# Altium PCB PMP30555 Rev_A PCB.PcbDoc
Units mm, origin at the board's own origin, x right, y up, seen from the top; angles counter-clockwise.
Board outline 51.56 x 17.27 mm, 2 copper layers (Top Layer, Bottom Layer), stack 1.575 mm thick; 27 components, 19 nets, 71 pads, 26 vias.
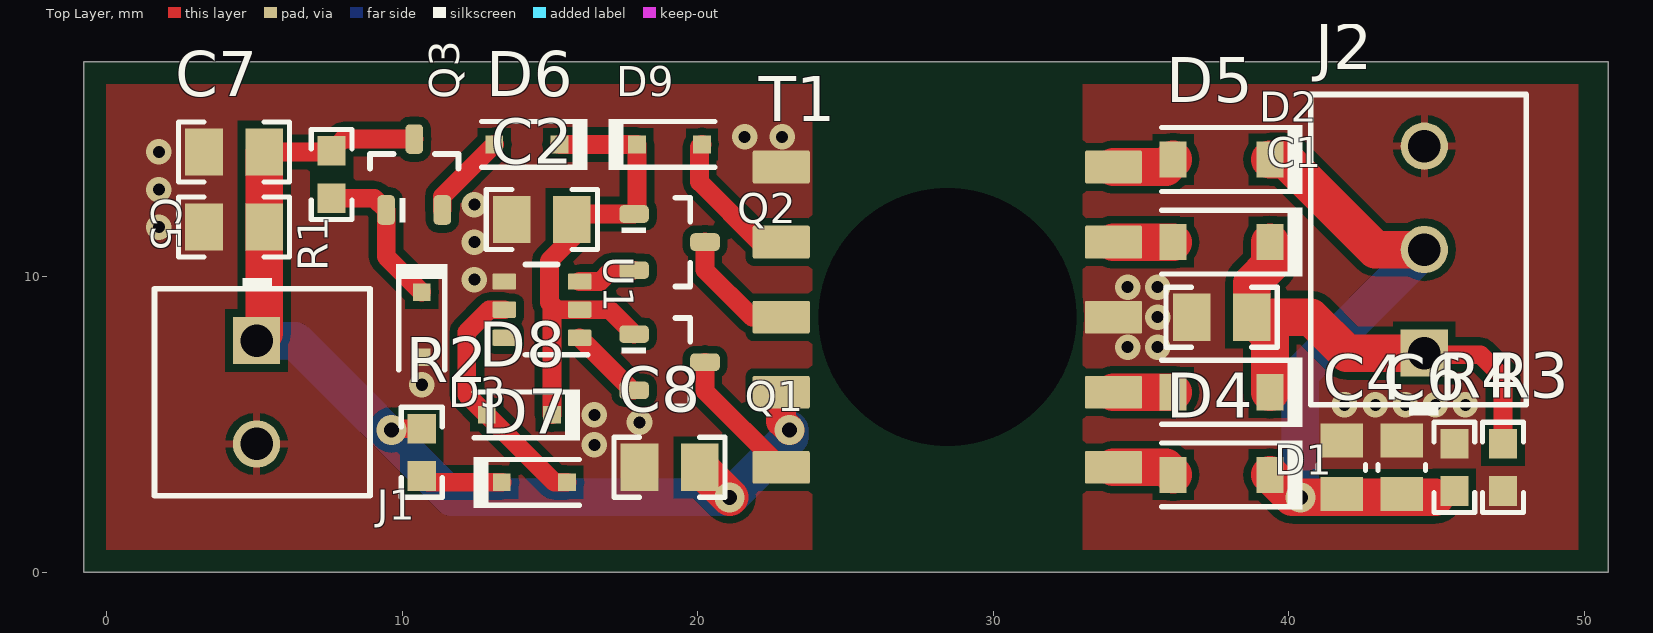
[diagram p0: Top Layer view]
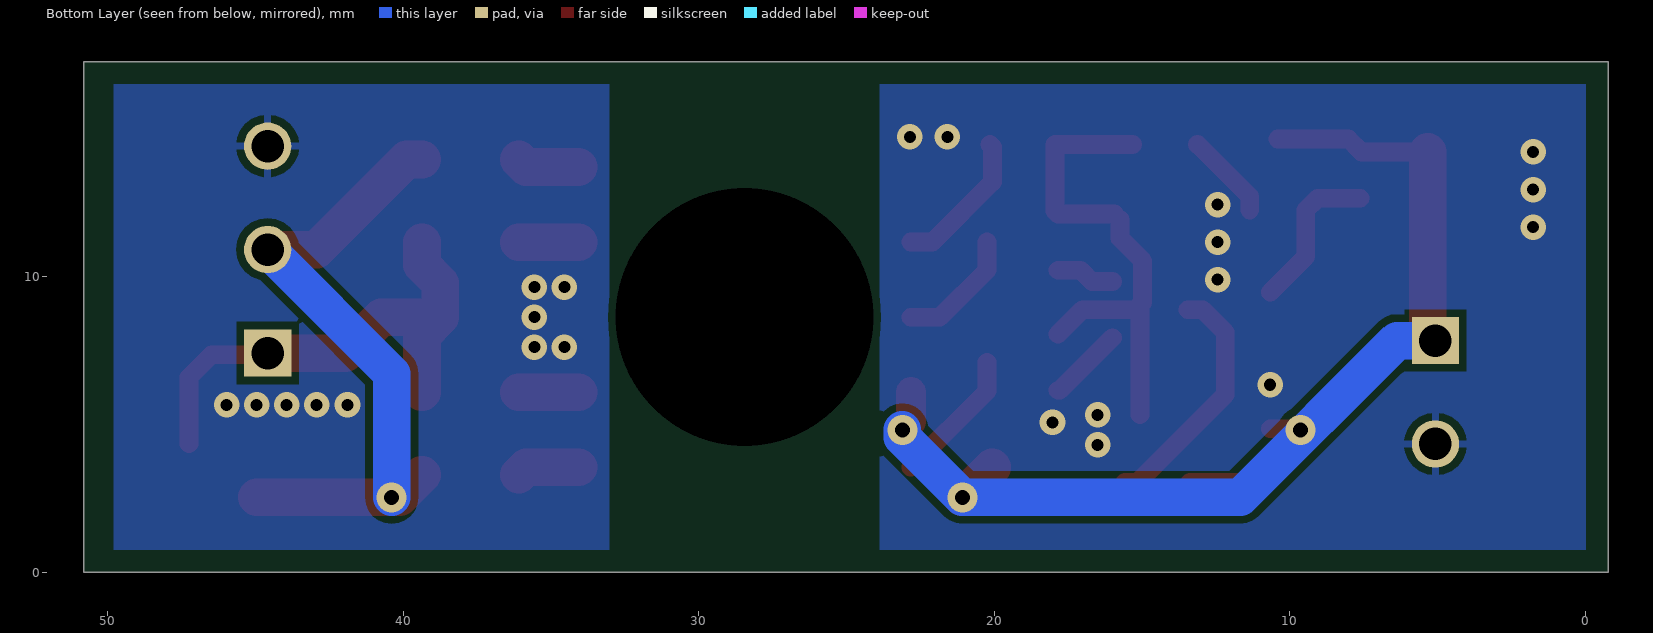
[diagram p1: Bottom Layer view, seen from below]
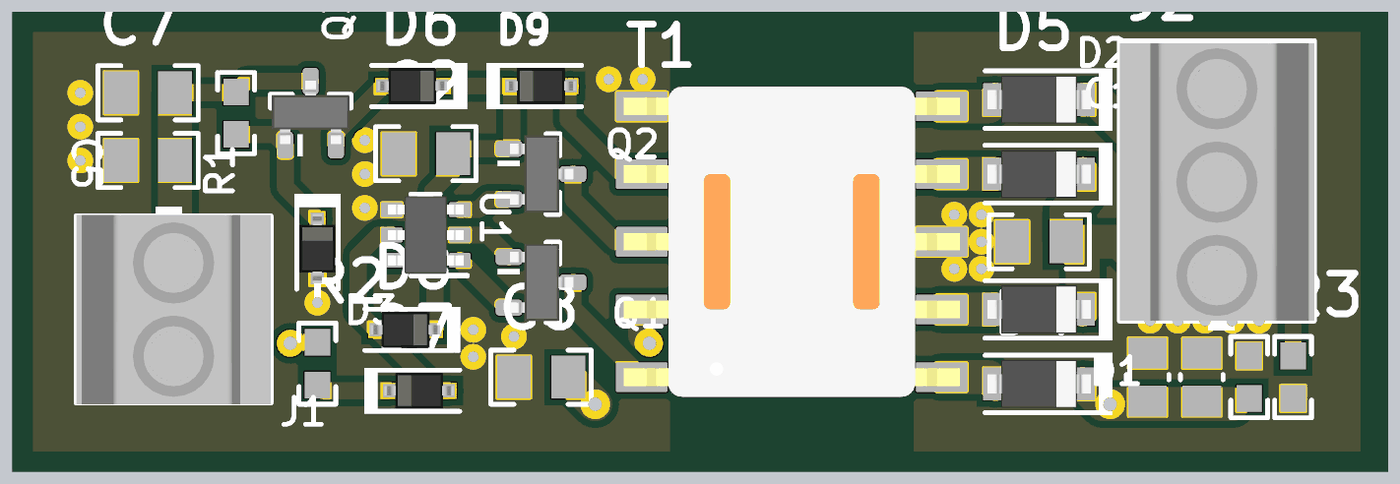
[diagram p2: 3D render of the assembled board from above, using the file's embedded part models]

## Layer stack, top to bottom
Top Solder: solder mask 0.0102, Solder Resist, Dk 3.5
Top Layer: signal copper 0.0356
Dielectric1: core 1.5037, FR-4, Dk 4.8
Bottom Layer: signal copper 0.0356
Bottom Solder: solder mask 0.0102, Solder Resist, Dk 3.5

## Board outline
-0.762,0 -0.762,17.272 50.8,17.272 50.8,0

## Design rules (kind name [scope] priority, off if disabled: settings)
AcuteAngle [All] p1: minimum=4.50000000000000E+0001 checktracksonly=FALSE
AssemblyTestPointUsage [All] p1: valid=2
BoardOutlineClearance BoardOutlineClearance_MountingHoles [OnCopper and InComponentClass('Mounting Holes')] p1: gap=1.016 ignorepadtopadclearanceinfootprint=FALSE
BoardOutlineClearance BoardOutlineClearance_Poly [OnCopper and IsPoly] p2: gap=0.635 ignorepadtopadclearanceinfootprint=FALSE
BoardOutlineClearance [OnCopper and Not InComponentClass('Logo') and not InComponentClass('FiducialMark') and not InRegion(1000,500,4000,800) and not InPoly] p3: gap=1.905 ignorepadtopadclearanceinfootprint=FALSE
Clearance Clearance_4 [InNamedPolygon('TOP_LAYER_GND-S_P006')] p1: gap=0.254 ignorepadtopadclearanceinfootprint=FALSE except(0: Arc-Hole Track-Hole SMDPad-Hole THPad-Hole Via-Hole Fill-Hole Poly-Hole Region-Hole Text-Hole)
Clearance Clearance_3 [InNamedPolygon('BOTTOM_LAYER_GND-S_P004')] p2: gap=0.254 ignorepadtopadclearanceinfootprint=FALSE except(0: Arc-Hole Track-Hole SMDPad-Hole THPad-Hole Via-Hole Fill-Hole Poly-Hole Region-Hole Text-Hole)
Clearance Clearance_2 [InNamedPolygon('BOTTOM_LAYER_GND-P_P002')] p3: gap=0.254 ignorepadtopadclearanceinfootprint=FALSE except(0: Arc-Hole Track-Hole SMDPad-Hole THPad-Hole Via-Hole Fill-Hole Poly-Hole Region-Hole Text-Hole)
Clearance Clearance_1 [InNamedPolygon('TOP_LAYER_GND-P_P000')] p4: gap=0.254 ignorepadtopadclearanceinfootprint=FALSE except(0: Arc-Hole Track-Hole SMDPad-Hole THPad-Hole Via-Hole Fill-Hole Poly-Hole Region-Hole Text-Hole)
Clearance Clearance_Keepouts [((IsTrack Or IsArc) And Not InPoly) And IsFree and IsKeepOut vs ((IsTrack Or IsArc) And Not InPoly) And IsFree and IsKeepOut] p5: gap=0 ignorepadtopadclearanceinfootprint=FALSE
Clearance Clearance_Poly [InPolygon] p6: gap=0.254 ignorepadtopadclearanceinfootprint=FALSE
Clearance Clearance_FiducialMark [IsKeepOut and InComponentClass('FiducialMark') vs IsPad and InComponentClass('FiducialMark')] p7: gap=0 ignorepadtopadclearanceinfootprint=FALSE
Clearance [All] p8: gap=0.2 ignorepadtopadclearanceinfootprint=FALSE except(0: Arc-Hole Track-Hole SMDPad-Hole THPad-Hole Via-Hole Fill-Hole Poly-Hole Region-Hole Text-Hole)
ComponentClearance ComponentClearance_MountingHoles_FiducialMarks [InComponentClass('Mounting Holes') vs InComponentClass('FiducialMark')] p1: gap=1.27 collisioncheckmode=3 verticalgap=0.254 showdistances=FALSE
ComponentClearance ComponentClearance_Shunt [InComponentClass('Header') vs InComponentClass('Shunt')] p2: gap=0 collisioncheckmode=3 verticalgap=0 showdistances=FALSE
ComponentClearance ComponentClearance_Logo [InComponentClass('Logo')] p3: gap=1.27 collisioncheckmode=3 verticalgap=0.254 showdistances=FALSE
ComponentClearance ComponentClearance_ScrewToNut [(HasFootprint('NY PMS 440 0025 PH')) vs (HasFootprint('Keystone_1902C'))] p4: gap=0.127 collisioncheckmode=3 verticalgap=0.254 showdistances=FALSE
ComponentClearance ComponentClearance_MountingHoles [InComponentClass('Mounting Holes')] p5: gap=6.35 collisioncheckmode=3 verticalgap=2540 showdistances=FALSE
ComponentClearance ComponentClearance_SmallPassives [HasFootprint('0201*') or HasFootprint('0402*') or HasFootprint('0508') or HasFootprint('0603*') or HasFootprint('0612') or HasFootprint('0805*') or HasFootprint('0815*') or HasFootprint('0830*') or HasFootprint('1206*') or HasFootprint('1210*') or HasFootprint('1808*') or HasFootprint('1812*') or HasFootprint('1825*') or HasFootprint('2010*') or HasFootprint('2220*') or HasFootprint('2225*') or HasFootprint('2512*') or HasFootprint('2728*') or HasFootprint('3518*') vs HasFootprint('0201*') or HasFootprint('0402*') or HasFootprint('0508') or HasFootprint('0603*') or HasFootprint('0612') or HasFootprint('0805*') or HasFootprint('0815*') or HasFootprint('0830*') or HasFootprint('1206*') or HasFootprint('1210*') or HasFootprint('1808*') or HasFootprint('1812*') or HasFootprint('1825*') or HasFootprint('2010*') or HasFootprint('2220*') or HasFootprint('2225*') or HasFootprint('2512*') or HasFootprint('2728*') or HasFootprint('3518*')] p6: gap=0.38 collisioncheckmode=3 verticalgap=0.254 showdistances=FALSE
ComponentClearance ComponentClearance_THtoSMT [IsThruComponent vs IsSMTComponent] p7: gap=1.016 collisioncheckmode=3 verticalgap=0.762 showdistances=FALSE
ComponentClearance ComponentClearance_THtoTH [IsThruComponent vs IsThruComponent] p8: gap=0.762 collisioncheckmode=3 verticalgap=0.762 showdistances=FALSE
ComponentClearance [All] p9: gap=0.762 collisioncheckmode=3 verticalgap=0.254 showdistances=FALSE
DiffPairsRouting [All] p1: maxlimit=2.54 minlimit=0.254 mostfreqgap=0.254 toplayer_minwidth=0.381 toplayer_maxwidth=0.381 toplayer_prefwidth=0.381 bottomlayer_minwidth=0.381 bottomlayer_maxwidth=0.381 bottomlayer_prefwidth=0.381 maxuncoupledlength=25.4
FabricationTestPointUsage TestPointUsage [All] p1: valid=2 allowmultiple=FALSE
FabricationTestpoint Testpoint [All] p1: side=3 testpointundercomponent=TRUE minsize=1.016 maxsize=2.54 preferedsize=1.524 minholesize=0 maxholesize=1.016 preferedholesize=0.813 testpointgrid=0.025 allowsidetop=TRUE allowsidebottom=TRUE usegrid=TRUE gridtolerance=0
FanoutControl Fanout_LCC [IsLCC] p1: bgadir=Out bgaviamode=Centered fanoutstyle=Auto fanoutdirection=Alternating viagrid=0.025 // Fanout_LCC (Default Rule)
FanoutControl Fanout_BGA [IsBGA] p2: bgadir=Out bgaviamode=Centered fanoutstyle=Auto fanoutdirection=Alternating viagrid=0.025 // Fanout_BGA (Default Rule)
FanoutControl Fanout_Default [All] p4: bgadir=Out bgaviamode=Centered fanoutstyle=Auto fanoutdirection=Alternating viagrid=0.025 // Fanout_Default (Default Rule)
FanoutControl Fanout_Small [(CompPinCount < 5)] p5: bgadir=Out bgaviamode=Centered fanoutstyle=Auto fanoutdirection=OutThenIn viagrid=0.025 // Fanout_Small (Default Rule)
HoleSize [All] p1: absolutevalues=TRUE maxlimit=6.375 minlimit=0.3 maxpercent=80.000 minpercent=20.000
MinimumAnnularRing MinimumAnnularRing_ThermalPadVias [IsVia and InAnyComponent] p1: minimumring=0.15
MinimumAnnularRing [All] p2: minimumring=0.203
MinimumSolderMaskSliver MinimumSolderMaskSliver_Logo [InComponentClass('Logo') vs InComponentClass('Logo')] p1: minsoldermaskwidth=0.018
MinimumSolderMaskSliver [All] p2: minsoldermaskwidth=0.1
PlaneConnect [All] p1: planeconnectstyle=Relief reliefexpansion=0.254 reliefentries=4 reliefconductorwidth=0.254 reliefairgap=0.254
PolygonConnect [All] p1: thpad.connectstyle=Relief thpad.reliefconductorwidth=0.254 thpad.reliefentries=4 thpad.polygonreliefangle="90 Angle" thpad.airgapwidth=0.254 smdpad.connectstyle=Direct smdpad.reliefconductorwidth=0.254 smdpad.reliefentries=4 smdpad.polygonreliefangle="90 Angle" smdpad.airgapwidth=0.254 via.connectstyle=Direct via.reliefconductorwidth=0.254 via.reliefentries=4 via.polygonreliefangle="90 Angle" via.airgapwidth=0.254
RoutingVias ThermalPadVias [IsVia and InAnyComponent] p1: holewidth=0.3 width=0.5 viastyle="Through Hole" minholewidth=0.3 minwidth=0.6 maxholewidth=0.33 maxwidth=0.6
RoutingVias [All] p2: holewidth=0.406 width=0.864 viastyle="Through Hole" minholewidth=0.3 minwidth=0.66 maxholewidth=1.016 maxwidth=1.651
SilkToBoardRegionClearance [Not ((IsComment or IsDesignator) And (Hide <> 'False')) and not InRegion(1000,500,4000,800)] p1:
SilkToSilkClearance SilkToSilkClearance_Pb-FreeLogo [(HasFootprint('Pb-Free_Overlay_Medium') OR HasFootprint('Pb-Free_Overlay_Small')) vs (HasFootprint('Pb-Free_Overlay_Medium') OR HasFootprint('Pb-Free_Overlay_Small'))] p1: silktosilkclearance=0
SilkToSilkClearance [All] p2: silktosilkclearance=0.102
SilkToSolderMaskClearance SilkToComponentPadClearance [(IsPad or IsFill or IsRegion) and InAnycomponent] p1: minsilkscreentomaskgap=0.127 clearancetoexposedcopper=TRUE
SilkToSolderMaskClearance "Silk to Solder Mask Opening" [All] p2: minsilkscreentomaskgap=0.102 clearancetoexposedcopper=FALSE
SolderMaskExpansion [All] p1: expansion=0.05
Width [All] p1: maxlimit=2.54 minlimit=0.152 preferedwidth=0.254 checkconnectedcopper=TRUE
15 further rules are at their usual default settings.

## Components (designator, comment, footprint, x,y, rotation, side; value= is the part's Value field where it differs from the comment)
C1 "885012207026" 0805_HV 37.724,8.636 r180 top value=10uF
C2 "885012207026" 0805_HV 14.732,11.938 r180 top value=10uF
C4 "08053C225KAT2A" 0805_150 41.788,3.556 r90 top value=2.2uF
C5 "08055C105KAT2A" 0805_HV 4.318,11.684 r180 top value=1uF
C6 "08053C225KAT2A" 0805_150 43.82,3.556 r90 top value=2.2uF
C7 "08055C105KAT2A" 0805_HV 4.318,14.224 r180 top value=1uF
C8 "08055C105KAT2A" 0805_HV 19.05,3.556 r180 top value=1uF
D1 "MBR0540T1G" SOD-123 37.724,6.096 r180 top value=40V
D2 "MBR0540T1G" SOD-123 37.724,11.176 r180 top value=40V
D3 "BZT52C5V1S-7-F" SOD-323 10.668,8.382 r270 top value=5.1V
D4 "MBR0580-TP" SOD-123 37.724,3.302 r180 top value=80V
D5 "MBR0580-TP" SOD-123 37.724,13.97 r180 top value=80V
D6 "BAT54WS-7-F" SOD-323 14.224,14.478 r180 top value=30V
D7 "BZX384-C12,115" SOD-323 14.478,3.048 r0 top value=12V
D8 "BAT54WS-7-F" SOD-323 13.97,5.334 r180 top value=30V
D9 "BAT54WS-7-F" SOD-323 19.05,14.478 r0 top value=30V
J1 "39357-0002" MOLEX_39357-0002 5.08,6.096 r270 top
J2 "39357-0003" MOLEX_39357-0003 44.582,10.922 r90 top
Q1 "IRLML0030TRPBF" SOT-23 19.05,7.112 r0 top value=IRLML0100TRPbF
Q2 "IRLML0030TRPBF" SOT-23 19.05,11.176 r0 top value=IRLML0100TRPbF
Q3 "MMBT3904LT1G" SOT-23 10.414,13.462 r90 top value="40 V"
R1 "CRCW0603100KFKEA" 0603 7.62,13.462 r90 top value=100k
R2 "CRCW0603100KFKEA" 0603 10.668,4.064 r90 top value=100k
R3 "ERJ-3EKF1001V" 0603 47.244,3.556 r90 top value=1.00k
R4 "RCG060310K0FKEA" 0603 45.598,3.556 r270 top value=10.0k
T1 "750317843R00" Wurth_750317843R00 28.448,8.636 r90 top
U1 "SN6505BDBVR" DBV0006A_L 14.732,8.89 r180 top

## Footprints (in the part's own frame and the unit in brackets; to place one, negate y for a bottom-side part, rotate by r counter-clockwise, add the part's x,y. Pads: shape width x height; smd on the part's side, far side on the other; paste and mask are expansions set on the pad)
0603 [mm] "0603 from SM-752 data"
  rect 1x0.95 smd: 1(-0.8,0) 2(0.8,0)
  silkscreen extent -1.52,-0.69 1.52,0.69, body extent -0.87,-0.47 0.87,0.47, height 1
0805_150 [mm] "0805 / 1.5 mm height"
  rect 1.15x1.45 smd: 1(-0.9,0) 2(0.9,0)
  silkscreen extent -0.1,-0.8 0.1,0.8, body extent -1.1,-0.72 1.1,0.72, height 1.5
0805_HV [mil] "0805 with 30mil clearance between pads"
  rect 50x63 smd: 1(-40,0) 2(40,0)
  silkscreen extent -74,-40 74,40, body extent -43,-29 43,29, height 57
DBV0006A_L [mm] "SOT23, 6-Leads, Body 2.9x1.6mm, Pitch 0.95mm, Lead Span 2.8mm, IPC High Density"
  rrect18% 0.8x0.55 smd: 1(-1.275,0.95) 2(-1.275,0) 3(-1.275,-0.95) 4(1.275,-0.95) 5(1.275,0) 6(1.275,0.95)
  silkscreen extent -1.55,-1.53 0.55,1.53, body extent -1.42,-1.46 1.42,1.46, height 1.12
MOLEX_39357-0002 [mm] "Terminal Block, 3.5 mm, 2x1, TH"
  rect 1.6x1.6 hole 1.1: 1(-1.75,0)
  round 1.6 hole 1.1: 2(1.75,0)
  silkscreen extent -3.86,-3.45 3.5,3.84, body extent -3.55,-3.45 3.56,3.84, height 8.51
MOLEX_39357-0003 [mm] "Terminal Block, 3.5 mm, 3x1, TH"
  rect 1.6x1.6 hole 1.1: 1(-3.5,0)
  round 1.6 hole 1.1: 2(0,0) 3(3.5,0)
  silkscreen extent -5.61,-3.45 5.25,3.84, body extent -5.25,-3.45 5.16,3.84, height 8.51
SOD-123 [mm] "On Semi recommended land pattern"
  rect 0.915x1.22 smd: 1(-1.637,0) 2(1.637,0)
  silkscreen extent -2.74,-1.17 2.03,1.17, body extent -1.93,-0.9 1.93,0.9, height 1.35
SOD-323 [mm] "NXP recommended land pattern"
  rect 0.6x0.6 smd paste-0.05: 1(-1.1,0) 2(1.1,0)
  silkscreen extent -2.06,-0.86 1.53,0.86, body extent -1.3,-0.67 1.3,0.68, height 1.1
SOT-23 [mm] "SOT23, 3-Leads, Body 2.9x1.3mm, Pitch 0.95mm, Lead Span 2.5mm, IPC Medium Density"
  rrect50% 1x0.6 smd: 1(-1.2,0.95) 2(-1.2,-0.95) 3(1.2,0)
  silkscreen extent -1.63,-1.5 0.7,1.5, body extent -1.16,-1.45 1.21,1.45, height 1
Wurth_750317843R00 [mm] "SMD, 10-Leads, Body 9.25x11.63mm, Pitch 2.54mm"
  rrect9% 1.11x1.93 smd: 1(-5.08,5.62) 2(-2.54,5.62) 3(0,5.62) 4(2.54,5.62) 5(5.08,5.62) 6(5.08,-5.62) 7(2.54,-5.62) 8(0,-5.62) 9(-2.54,-5.62) 10(-5.08,-5.62)
  round 8.43 hole 8.73 unplated mask+0.102: ""(0,0)
  body extent -5.82,-6.3 5.81,6.3, height 1.98

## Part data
C1 C2: library part CMP-0007691-2, "CAP, CERM, 10 uF, 10 V, +/- 10%, X7R, 0805", Cap_Case=0805, Manufacturer="Wurth Elektronik", Supplier Part Number 1=710-885012207026, TempCo=X7R, Tolerance_%=10%, Value1=Unknown, Value2=10V, ValueDisplayed=10uF
C4 C6: library part CMP-0007573-2, "CAP, CERM, 2.2 uF, 25 V, +/- 10%, X7R, 0805", Cap_Case=0805, Manufacturer=AVX, Supplier Part Number 1=478-5719-1-ND, TempCo=X7R, Tolerance_%=10%, Value1=Unknown, Value2=25V, ValueDisplayed=2.2uF
C5 C7 C8: library part CMP-0007634-2, "CAP, CERM, 1 uF, 50 V, +/- 10%, X7R, 0805", Cap_Case=0805, Manufacturer=AVX, Supplier Part Number 1=478-7956-1-ND, TempCo=X7R, Tolerance_%=10%, Value1=Unknown, Value2=50V, ValueDisplayed=1uF
D1 D2: "Diode, Schottky, 40 V, 0.5 A, SOD-123", Manufacturer="ON Semiconductor", Supplier Part Number 1=MBR0540T1GOSCT-ND, Value1=0.5A, Value2=0.51V
D3: library part CMP-0005865-1, "Diode, Zener, 5.1 V, 200 mW, SOD-323", Manufacturer="Diodes Inc.", Power_W=200mW, Supplier Part Number 1=BZT52C5V1S-FDICT-ND, Value1=0.2W
D4 D5: library part CMP-0077000-1, "Diode, Schottky, 80 V, 0.5 A, SOD-123", Manufacturer="Micro Commercial Components", Supplier Part Number 1=MBR0580-TPMSCT-ND, Value1=0.5A, Value2=0.8V
D6 D8 D9: library part CMP-0028458-1, "Diode, Schottky, 30 V, 0.2 A, SOD-323", Manufacturer="Diodes Inc.", Supplier Part Number 1=BAT54WS-FDICT-ND, Value1=0.2A, Value2=0.7V
D7: library part CMP-0005843-2, "Diode, Zener, 12 V, 300 mW, SOD-323", Manufacturer="NXP Semiconductor", Power_W=300mW, Supplier Part Number 1=568-6279-1-ND, Value1=0.3W
J1: library part CMP-0055341-1, "Terminal Block, 3.5 mm, 2x1, Tin, TH", Manufacturer=Molex, Supplier Part Number 1=WM7877-ND
J2: library part CMP-0055340-1, "Terminal Block, 3.5 mm, 3x1, Tin, TH", Manufacturer=Molex, Supplier Part Number 1=WM7878-ND
Q1 Q2: library part CMP-0000635-1, "MOSFET, N-CH, 100 V, 1.6 A, SOT-23", Alternate Manufacturer=None, Manufacturer="International Rectifier", PartNumber=IRLML0100TRPbF, Supplier Part Number 1=IRLML0100TRPBFTR-ND, Value1=0, Value2="2.5 nC"
Q3: library part "MMBT3904LT1G, ON Semiconductor", "Transistor, NPN, 40 V, 0.2 A, SOT-23", Manufacturer="ON Semiconductor", Supplier Part Number 1=MMBT3904LT1GOSCT-ND, Value1="0.2 A", Value2=300
R1 R2: library part CMP-0021990-4, "RES, 100 k, 1%, 0.1 W, AEC-Q200 Grade 0, 0603", Manufacturer=Vishay-Dale, Power_W=100mW, Supplier Part Number 1=541-100KHCT-ND, TempCo="100 ppm/C", Tolerance_%=1%, Value2=0.1W, Value_Code=100k
R3: library part CMP-0022680-4, "RES, 1.00 k, 1%, 0.1 W, 0603", Manufacturer=Panasonic, Power_W=100mW, Supplier Part Number 1=P1.00KHCT-ND, TempCo="100 ppm/C", Tolerance_%=1%, Value2=0.1W, Value_Code=1k00, ValueDisplayed=1.00k
R4: library part CMP-0023337-3, "RES, 10.0 k, 1%, 0.1 W, 0603", Manufacturer="Vishay Draloric", Power_W=100mW, Supplier Part Number 1=541-1784-1-ND, TempCo="100 ppm/C", Tolerance_%=1%, Value2=0.1W, Value_Code=10k0, ValueDisplayed=10.0k
T1: library part CMP-0083966-1, "Transformer, 3430 uH, SMT", Manufacturer="Wurth Elektronik"
U1: library part CMP-0076095-1, "Low-Noise 1 A, 420 kHz Transformer Driver, DBV0006A (SOT-23-6)", Alternate Manufacturer="Texas Instruments", Alternate PartNumber=SN6505BDBVT

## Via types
v1: diameter 0.864, hole 0.406, Top Layer to Bottom Layer, 22 vias
v2: diameter 1.016, hole 0.508, Top Layer to Bottom Layer, 4 vias

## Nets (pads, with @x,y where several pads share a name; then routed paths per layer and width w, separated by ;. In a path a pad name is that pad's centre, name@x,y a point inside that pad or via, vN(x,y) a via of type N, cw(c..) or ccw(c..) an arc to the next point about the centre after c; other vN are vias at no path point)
GND-P: C2.2 C5.2 C7.2 C8.2 D3.2 J1.2 T1.5 U1.4
  other v1: 16.51,4.318 18.034,5.08 16.51,5.334 10.668,6.35 12.446,9.906 12.446,11.176 1.778,11.684 12.446,12.446 1.778,12.954 1.778,14.224 21.59,14.732 22.86,14.732
GND-S: C1.2 C4.2 C6.2 J2.3 R3.1 R4.1 T1.8
  other v1: 41.882,5.672 42.926,5.672 43.942,5.672 44.958,5.672 45.974,5.672 34.544,7.62 35.56,7.62 35.56,8.636 34.544,9.652 35.56,9.652
NetC1_1: C1.1 D1.1 D2.1 J2.1 R3.2 | length 17.1
  Top Layer w0.635: J2.1@44.638,7.366 46.482,7.366 47.244,6.604 R3.2
  Top Layer w1.27: D1.1 39.362,8.014 C1.1 ; D2.1 39.362,10.406 38.74,9.784 C1.1 ; J2.1 41.956,7.422 40.742,8.636 C1.1
NetC2_1: C2.1 D6.1 D8.1 D9.1 Q1.1 Q2.1 U1.2 | length 17.1
  Top Layer w0.635: D8.1 15.07,9.052 ; D6.1 D9.1 17.95,12.226 Q2.1 C2.1@15.936,12.126 ; C2.1 15.748,11.302 14.986,10.54 14.986,9.136 15.07,9.052 ; Q1.1 17.022,8.89 U1.2 15.232,8.89 15.07,9.052
NetC4_1: C4.1 C6.1 D4.1 D5.1 J2.2 R4.2 | length 22.5
  Top Layer w1.27: D4.1 40.124,2.54 v2(40.386,2.54) 44.958,2.54 ; D5.1 39.878,13.97 42.926,10.922 J2.2
  Bottom Layer w1.27: v2(40.386,2.54) 40.386,6.726 J2.2
NetC5_1: C5.1 C7.1 C8.1 J1.1 Q3.3 R1.2 R2.2 T1.2 | length 36.9
  Top Layer w0.635: C7.1 7.582,14.224 R1.2 8.02,14.662 Q3.3 ; v2(9.652,4.826) 9.69,4.864 R2.2
  Top Layer w1.016: T1.2 22.828,5.112 v2(23.114,4.826)
  Top Layer w1.27: J1.1 5.334,8.1 C5.1 C7.1 ; C8.1 v2(21.082,2.54)
  Bottom Layer w1.27: J1.1 6.378,7.846 11.684,2.54 v2(21.082,2.54) 23.114,4.572 v2(23.114,4.826)
NetD1_2: D1.2 T1.9 | length 2
  Top Layer w1.27: T1.9 D1.2
NetD2_2: D2.2 T1.7 | length 2
  Top Layer w1.27: T1.7 D2.2
NetD3_1: D3.1 Q3.1 R1.1 | length 5.3
  Top Layer w0.635: R1.1 9.064,12.662 Q3.1 9.464,10.686 D3.1
NetD4_2: D4.2 T1.10 | length 2.1
  Top Layer w1.27: T1.10 35.833,3.556 D4.2
NetD5_2: D5.2 T1.6 | length 2.1
  Top Layer w1.27: T1.6 35.833,13.716 D5.2
NetD6_2: D6.2 Q3.2 | length 2.9
  Top Layer w0.635: Q3.2 11.364,12.718 D6.2
NetD7_1: D7.1 R2.1 | length 2.5
  Top Layer w0.635: R2.1@10.884,3.048 D7.1
NetD7_2: D7.2 D8.2 U1.5 | length 8.3
  Top Layer w0.635: U1.5 12.954,8.89 12.192,8.128 12.192,6.012 D8.2 15.156,3.048 D7.2
NetD9_2: D9.2 T1.4 | length 4.9
  Top Layer w0.635: D9.2 20.066,14.394 20.066,13.208 22.098,11.176 T1.4
NetQ1_2: Q1.2 U1.1 | length 2.6
  Top Layer w0.635: U1.1 17.785,6.162 Q1.2
NetQ1_3: Q1.3 T1.1 | length 4.6
  Top Layer w0.635: Q1.3 20.25,6.134 T1.1
NetQ2_2: Q2.2 U1.3 | length 2
  Top Layer w0.635: U1.3 16.698,9.84 17.084,10.226 Q2.2
NetQ2_3: Q2.3 T1.3 | length 4.2
  Top Layer w0.635: Q2.3 20.25,10.23 21.844,8.636 T1.3
pads on no net: T1. U1.6

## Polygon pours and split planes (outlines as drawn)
GND-S on Top Layer "Top Layer-No Net 1" (solid, pour order 4): 33.02,16.51 49.784,16.51 49.784,0.762 33.02,0.762
GND-P on Top Layer "Top Layer-No Net" (solid, pour order 0): 0,16.51 23.876,16.51 23.876,0.762 0,0.762
GND-S on Bottom Layer "Top Layer-No Net 1" (solid, pour order 6): 33.02,16.51 49.784,16.51 49.784,0.762 33.02,0.762
GND-P on Bottom Layer "Top Layer-No Net" (solid, pour order 2): 0,16.51 23.876,16.51 23.876,0.762 0,0.762

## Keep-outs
Keep-Out Layer:
  text ".Layer_Name" at 14.656,-21.806 h1.52

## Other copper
Top Layer:
  text ".Layer_Name" at 14.656,-21.806 h1.52
Bottom Layer:
  text ".Layer_Name" at 14.656,-21.806 h1.52

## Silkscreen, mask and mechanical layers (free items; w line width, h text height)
Top Overlay:
  text ".Layer_Name" at 14.656,-21.806 h1.52
Bottom Overlay:
  text ".Layer_Name" at 14.656,-21.806 h1.52
Top Paste:
  text ".Layer_Name" at 14.656,-21.806 h1.52
Bottom Paste:
  text ".Layer_Name" at 14.656,-21.806 h1.52
Top Solder:
  text ".Layer_Name" at 14.656,-21.806 h1.52
  text ".Layer_Name" at 14.656,-21.806 h1.52
Bottom Solder:
  text "A" at 6.096,14.164 h2.54
  text "'.PRJ_Number'.PCB_Rev-" at 19.05,14.164 h2.75
  text ".Layer_Name" at 14.656,-21.806 h1.52
Drill Guide:
  text ".Layer_Name" at 14.656,-21.806 h1.52
M1 Board Outline:
  the board outline again, w0.254
  text ".Layer_Name" at 14.656,-21.806 h1.52
M2 Board Dimensions:
  rectangle: 0,-6.985 3.175,-3.81
  rectangle: 3.175,-10.16 12.7,-6.985
  lines w0.178: 0,-6.985 25.4,-6.985 ; 3.175,-10.16 3.175,-3.81 ; 6.35,-10.16 6.35,-3.81 ; 12.7,-10.16 12.7,-3.81 ; 19.05,-10.16 19.05,-3.81 ; 0,-10.16 25.4,-10.16 25.4,-3.81 0,-3.81 0,-10.16
  text ".Layer_Name" at 14.656,-21.806 h1.52
M3 3D STEP Top:
  text ".Layer_Name" at 14.656,-21.806 h1.52
M4 3D STEP Bottom:
  text ".Layer_Name" at 14.656,-21.806 h1.52
M5 Assembly Top:
  lines w0.254: -7.417,-23.626 160.223,-23.626 ; -7.417,-18.462 160.274,-18.462 ; -7.417,-13.297 -7.417,-28.791 94.31,-28.791 160.274,-28.791 160.274,-13.297 -7.404,-13.297 -7.404,-28.791 32.614,-28.791 ; 55.194,-28.791 55.194,-13.297 ; 87.376,-18.462 87.376,-13.297 ; 108.712,-18.462 108.712,-13.297 ; 124.511,-28.956 124.511,-23.804
  text "COMPONENTS MARKED 'DNP' SHOULD NOT BE POPULATED." at 29.299,-8.09 h1.52
  text "ASSEMBLY VARIANT:" at 29.286,-11.024 h1.52
  text ".VariantName" at 55.601,-11.024 h1.52
  text "PCB VIEWED FROM TOP SIDE" at -5.804,-16.654 h1.52
  text "BOARD #:" at 57.099,-16.654 h1.52
  text ".PRJ_Number" at 70.955,-16.654 h1.52
  text "REV:" at 92.405,-16.654 h1.52
  text ".PCB_Rev" at 99.809,-16.654 h1.52
  text "SVN REV:" at 113.69,-16.654 h1.52
  text ".VersionControl_RevNumber" at 126.543,-16.654 h1.52
  text "TID #:" at 57.099,-21.819 h1.52
  text ".TID" at 70.955,-21.819 h1.52
  text "PLOT NAME =" at -5.804,-27.034 h1.52
  text ".plot_File_Name" at 14.656,-27.034 h1.52
  text "GENERATED    :" at 57.15,-27.034 h1.52
  text ".Print_Date" at 79.235,-27.034 h1.52
  text ".Print_Time" at 97.752,-27.034 h1.52
  text "TEXAS INSTRUMENTS" at 129.87,-27.034 h1.52
M6 Assembly Bottom:
  lines w0.254: -7.429,-18.474 160.261,-18.474 ; -7.379,-23.639 160.261,-23.639 ; 28.334,-28.969 28.334,-23.817 ; 44.133,-18.474 44.133,-13.31 ; 65.468,-18.474 65.468,-13.31 ; 97.65,-28.804 97.65,-13.31 ; 120.231,-28.804 160.249,-28.804 160.249,-13.31 -7.429,-13.31 -7.429,-28.804 58.534,-28.804 160.261,-28.804 160.261,-13.31
  text "COMPONENTS MARKED 'DNP' SHOULD NOT BE POPULATED." at 154.991,-8.077 h1.52
  text ".VariantName" at 128.473,-11.024 h1.52
  text "ASSEMBLY VARIANT:" at 154.864,-11.024 h1.52
  text ".VersionControl_RevNumber" at 26.302,-16.667 h1.52
  text "SVN REV:" at 39.154,-16.667 h1.52
  text ".PCB_Rev" at 53.035,-16.667 h1.52
  text "REV:" at 60.439,-16.667 h1.52
  text ".PRJ_Number" at 81.89,-16.667 h1.52
  text "BOARD #:" at 95.745,-16.667 h1.52
  text "PCB VIEWED FROM BOTTOM SIDE" at 158.648,-16.667 h1.52
  text ".TID" at 81.89,-21.831 h1.52
  text "TID #:" at 95.745,-21.831 h1.52
  text "TEXAS INSTRUMENTS" at 22.974,-27.047 h1.52
  text ".Print_Time" at 55.093,-27.047 h1.52
  text ".Print_Date" at 73.609,-27.047 h1.52
  text "GENERATED    :" at 95.694,-27.047 h1.52
  text ".plot_File_Name" at 138.189,-27.047 h1.52
  text "PLOT NAME =" at 158.648,-27.047 h1.52
M9 Title Sheet:
  drawing of 57 lines, arcs and shapes, not listed
  text "1" at 18.792,204.127 h1.78
  text "2" at 82.182,204.127 h1.78
  text "3" at 145.411,204.127 h1.78
  text "4" at 209.08,204.127 h1.78
  text "5" at 272.555,204.127 h1.78
  text "6" at 336.182,204.127 h1.78
  text "A" at -10.579,175.095 h1.78
  text "A" at 365.341,175.095 h1.78
  text "B" at -10.579,114.643 h1.78
  text "B" at 365.341,114.643 h1.78
  text "C" at -10.579,54.318 h1.78
  text "C" at 365.341,54.318 h1.78
  text "PROJECT TITLE:" at 288.125,7.048 h1.14
  text ".PRJ_Title" at 289.395,3.662 h1.78
  text "DESIGNED FOR:" at 288.125,-0.597 h1.14
  text ".PRJ_Customer" at 289.395,-4.153 h1.78
  text "D" at -10.579,-5.88 h1.78
  text "D" at 365.341,-5.88 h1.78
  text "FILE NAME:" at 288.125,-8.217 h1.14
  text ".PCB_File_Name_No_Path" at 289.395,-11.265 h1.78
  text "Texas Instruments (TI) and/or its licensors do not warrant the accuracy or completeness of this specification" at 161.9,-15.376 h1.14
  text "ENGINEER:" at 288.125,-15.583 h1.14
  text "LAYOUT BY:" at 326.352,-15.583 h1.14
  text "or any information contained therein. TI and/or its licensors do not warrant that this design will meet" at 160.757,-18.237 h1.14
  text ".PRJ_Engineer" at 289.395,-19.52 h1.78
  text ".PCB_Layout" at 327.635,-19.52 h1.78
  text "the specifications, will be suitable for your application or fit for any particular purpose, or will operate in" at 160.757,-21.099 h1.14
  text ".Layer_Name" at 14.656,-21.806 h1.52
  text "ALTIUM DESIGNER VERSION:" at 326.352,-23.457 h1.14
  text "an implementation. TI and/or its licensors do not warrant that the design is production worthy. You should" at 160.757,-23.961 h1.14
  text "completely validate and test your design implementation to confirm the system functionality for your application." at 161.9,-26.822 h1.14
  text ".print_Scale" at 289.395,-26.843 h1.78
  text ".Application_BuildNumber" at 327.635,-26.843 h1.78
  text "1" at 18.792,-32.093 h1.78
  text "2" at 82.182,-32.093 h1.78
  text "3" at 145.411,-32.093 h1.78
  text "4" at 209.08,-32.093 h1.78
  text "5" at 272.555,-32.093 h1.78
  text "6" at 336.182,-32.093 h1.78
M10 Fab Notes:
  drawing of 189 lines, arcs and shapes, not listed
  text "DESIGN INFORMATION" at 314.503,161.447 h1.52
  text "MIN. TRACK WIDTH:" at 298.131,158.091 h1.52
  text "8" at 325.976,158.091 h1.52
  text "MIL" at 329.907,158.091 h1.52
  text "MIN. CLEARANCE:" at 298.131,154.938 h1.52
  text "0.2" at 324.452,154.938 h1.52
  text "mm" at 329.907,154.938 h1.52
  text "MIN. VIA PAD SIZE:" at 298.131,151.785 h1.52
  text "24" at 325.214,151.785 h1.52
  text "MIL" at 329.907,151.785 h1.52
  text "0.05mm (2MIL)" at 315.784,148.486 h1.52
  text "MINIMUM ANNULAR RING" at 289.769,148.277 h1.52
  text "EXTERNAL" at 333.768,148.277 h1.52
  text "PER" at 294.849,145.48 h1.52
  text "IPC-D-275 CLASS 2 LEVEL C" at 300.437,145.48 h1.52
  text "MIL, HOLES" at 338.238,142.928 h1.52
  text "+/-" at 328.27,142.709 h1.52
  text "+/-" at 349.961,142.709 h1.52
  text "REGISTRATION TOLERANCES:" at 289.769,142.682 h1.52
  text "METAL" at 320.243,142.682 h1.52
  text "5" at 334.879,142.683 h1.52
  text "3" at 356.037,142.683 h1.52
  text "MIL" at 358.99,142.682 h1.52
  text "HOLE SIZE TOLERANCE (UNLESS OTHERWISE SPECIFIED):" at 289.769,140.185 h1.52
  text "+/-" at 349.961,140.112 h1.52
  text "3" at 356.037,140.085 h1.52
  text "MIL" at 358.99,140.085 h1.52
  text "MATERIAL:" at 287.87,136.589 h1.52
  text "FR-4 High Tg" at 312.926,133.324 h1.52
  text "X" at 309.257,133.122 h1.52
  text "FR-408" at 298.563,133.007 h1.52
  text "OTHER" at 336.358,133.007 h1.52
  text "62 MIL (1.6mm) +/-10%" at 306.694,129.374 h1.52
  text "X" at 303.643,129.312 h1.52
  text "THICKNESS:" at 289.769,129.165 h1.52
  text "OTHER" at 339.33,129.165 h1.52
  text "TOLERANCE:" at 289.769,125.652 h1.52
  text "X" at 311.314,125.652 h1.52
  text "ANSI IPC-6012 TYPE 3 CLASS 2" at 315.836,125.652 h1.52
  text "OTHER +/-" at 315.835,121.989 h1.52
  text "BOW & TWIST:" at 289.769,118.302 h1.52
  text "X" at 311.314,118.302 h1.52
  text "ANSI IPC-6012 TYPE 3 CLASS 2" at 315.836,118.302 h1.52
  text "OTHER +/-" at 315.835,114.576 h1.52
  text "DRILLING:" at 287.87,111.258 h1.52
  text "NC_DRILL FILES" at 332.599,108.586 h1.52
  text "REFERENCE:" at 289.769,108.486 h1.52
  text "X" at 306.463,108.484 h1.52
  text "AS SHOWN" at 310.984,108.486 h1.52
  text "X" at 329.348,108.486 h1.52
  text "OTHER" at 340.168,104.873 h1.52
  text "PTH COPPER THICKNESS:" at 289.761,104.783 h1.52
  text "X" at 318.697,104.783 h1.52
  text "20-30 um" at 321.948,104.783 h1.52
  text "BOARD FINISH:" at 287.87,101.034 h1.52
  text "SILKSCREEN:" at 291.812,98.237 h1.52
  text "X" at 316.14,98.237 h1.52
  text "TOP" at 319.112,98.237 h1.52
  text "X" at 329.094,98.237 h1.52
  text "BOTTOM" at 332.091,98.237 h1.52
  text "SILKSCREEN COLOR:" at 291.812,94.295 h1.52
  text "X" at 316.115,94.295 h1.52
  text "WHITE" at 319.112,94.295 h1.52
  text "OTHER" at 332.091,94.295 h1.52
  text "X" at 319.442,90.652 h1.52
  text "GREEN" at 322.439,90.652 h1.52
  text "OTHER" at 338.136,90.652 h1.52
  text "SOLDER RESIST COLOR:" at 291.812,90.477 h1.52
  text "X" at 319.442,86.734 h1.52
  text "MATTE" at 322.439,86.734 h1.52
  text "SEMI-GLOSS" at 338.125,86.717 h1.52
  text "IMMERSION GOLD (ENIG)" at 314.819,82.345 h1.52
  text "ENEPIG" at 348.793,82.162 h1.52
  text "SURFACE FINISH:" at 287.87,82.136 h1.52
  text "X" at 310.298,82.136 h1.52
  text "IMM. TIN/SILVER OR EQUIV" at 296.24,78.649 h1.52
  text "OTHER" at 332.599,78.549 h1.52
  text "ARRAY/PANEL:" at 287.87,74.602 h1.52
  text "CUT AND TRIM PER M1 BOARD OUTLINE" at 314.819,74.393 h1.52
  text "N.C. ROUTE" at 314.819,70.94 h1.52
  text "X" at 332.295,70.94 h1.52
  text "V. SCORE" at 336.816,70.94 h1.52
  text "CERTIFICATION:" at 287.87,67.66 h1.52
  text "MATERIALS AND WORKMANSHIP FOR ALL PCBS" at 306.285,67.66 h1.52
  text "TO MEET OR EXCEED THE REQUIREMENTS OF:" at 306.285,65.271 h1.52
  text "X" at 297.078,62.003 h1.52
  text "ANSI IPC-A-600F CLASS ->" at 300.329,62.003 h1.52
  text "X" at 342.188,62.003 h1.52
  text "2" at 344.982,62.003 h1.52
  text "1" at 336.981,61.965 h1.52
  text "3" at 353.973,61.965 h1.52
  text "X" at 317.702,58.252 h1.52
  text "RoHS" at 320.953,58.252 h1.52
  text "OTHER" at 337.321,58.252 h1.52
  text "PER ORDER" at 347.407,58.252 h1.52
  text "ALL BOARDS MUST MEET OR EXCEED UL94-V0 REQUIREMENTS." at 288.569,54.345 h1.52
  text "PCB MUST BEAR THE UL94V-0 UL REGISTERED MATERIAL ID NUMBER" at 288.569,51.397 h1.52
  text "ADDITIONAL REQUIREMENTS:" at 287.87,47.094 h1.52
  text "MICROSECTION:" at 289.769,44.373 h1.52
  text "YES" at 312.775,44.373 h1.52
  text "REQUIRED" at 334.657,40.707 h1.52
  text "BARE BOARD ELEC. TEST:" at 289.769,40.634 h1.52
  text "NONE" at 322.935,40.634 h1.52
  text "X" at 331.66,40.634 h1.52
  text "PER ORDER" at 349.693,40.634 h1.52
  text "XX MIL VIAS REQUIRE NON-CONDUCTIVE FILL AND PLANARIZE" at 294.04,35.428 h1.5
  text "XX MIL VIAS REQUIRE CONDUCTIVE FILL AND PLANARIZE" at 294.243,32.787 h1.52
  text "OUTER XX MIL TRACES REQUIRE 50 OHM SINGLE-ENDED IMPEDANCE" at 294.218,28.637 h1.47
  text "LAYER 2 & 3 (INNER LAYERS) XX MIL WIDE, XX MIL SPACE / TRACES REQUIRE 100 OHM DIFFERENTIAL IMPEDANCE" at 294.015,22.65 h1.52
  text ".Layer_Name" at 14.656,-21.806 h1.52
M11 Gerber Information:
  lines w0.254: -7.417,-23.626 160.223,-23.626 ; -7.417,-18.462 160.274,-18.462 ; -7.417,-13.297 -7.417,-28.791 94.31,-28.791 160.274,-28.791 160.274,-13.297 -7.404,-13.297 -7.404,-28.791 32.614,-28.791 ; 55.194,-28.791 55.194,-13.297 ; 87.376,-18.462 87.376,-13.297 ; 108.712,-18.462 108.712,-13.297 ; 124.511,-28.956 124.511,-23.804
  text "ALL ARTWORK VIEWED FROM TOP SIDE" at -5.804,-16.654 h1.52
  text "BOARD #:" at 57.099,-16.654 h1.52
  text ".PRJ_Number" at 70.955,-16.654 h1.52
  text "REV:" at 92.405,-16.654 h1.52
  text ".PCB_Rev" at 99.809,-16.654 h1.52
  text "SVN REV:" at 113.69,-16.654 h1.52
  text ".VersionControl_RevNumber" at 126.543,-16.654 h1.52
  text "LAYER NAME =" at -5.804,-21.806 h1.52
  text "TID #:" at 57.099,-21.819 h1.52
  text ".TID" at 70.955,-21.819 h1.52
  text "PLOT NAME =" at -5.804,-27.034 h1.52
  text ".plot_File_Name" at 14.656,-27.034 h1.52
  text "GENERATED    :" at 57.15,-27.034 h1.52
  text ".Print_Date" at 79.235,-27.034 h1.52
  text ".Print_Time" at 97.752,-27.034 h1.52
  text "TEXAS INSTRUMENTS" at 129.87,-27.034 h1.52
M12 Stackup:
  drawing of 191 lines, arcs and shapes, not listed
  text "Layer" at 248.865,198.31 h1.52
  text "Name" at 259.277,198.31 h1.52
  text "Material" at 282.892,198.31 h1.52
  text "Thickness" at 304.731,198.31 h1.52
  text "Constant" at 321.236,198.31 h1.52
  text "Board Layer Stack" at 335.711,198.31 h1.52
  text "1" at 248.865,195.262 h1.52
  text "Top Overlay" at 259.277,195.262 h1.52
  text "2" at 248.865,192.214 h1.52
  text "Top Solder" at 259.277,192.214 h1.52
  text "Solder Resist" at 282.892,192.214 h1.52
  text "0.40mil" at 304.731,192.214 h1.52
  text "3.5" at 321.236,192.214 h1.52
  text "3" at 248.865,189.166 h1.52
  text "Top Layer" at 259.277,189.166 h1.52
  text "Copper" at 282.892,189.166 h1.52
  text "1.40mil" at 304.731,189.166 h1.52
  text "4" at 248.865,186.118 h1.52
  text "Dielectric1" at 259.277,186.118 h1.52
  text "FR-4" at 282.892,186.118 h1.52
  text "59.20mil" at 304.731,186.118 h1.52
  text "4.8" at 321.236,186.118 h1.52
  text "5" at 248.865,183.07 h1.52
  text "Bottom Layer" at 259.277,183.07 h1.52
  text "Copper" at 282.892,183.07 h1.52
  text "1.40mil" at 304.731,183.07 h1.52
  text "6" at 248.865,180.022 h1.52
  text "Bottom Solder" at 259.277,180.022 h1.52
  text "Solder Resist" at 282.892,180.022 h1.52
  text "0.40mil" at 304.731,180.022 h1.52
  text "3.5" at 321.236,180.022 h1.52
  text "7" at 248.865,176.975 h1.52
  text "Bottom Overlay" at 259.277,176.975 h1.52
  text ".Layer_Name" at 14.656,-21.806 h1.52
M13 Component Bodies Top:
  text ".Layer_Name" at 14.656,-21.806 h1.52
M14 Component Bodies Bottom:
  text ".Layer_Name" at 14.656,-21.806 h1.52
M15 Courtyards Top:
  text ".Layer_Name" at 14.656,-21.806 h1.52
M16 Courtyards Bottom:
  text ".Layer_Name" at 14.656,-21.806 h1.52
Drill Drawing:
  circle w0.254: c136.238,76.801 r0.702
  lines w0.254: 135.537,72.941 136.94,72.941 136.94,74.345 135.537,74.345 135.537,72.941 ; 135.537,79.607 135.888,79.607 136.238,79.257 136.589,79.607 136.94,79.607 136.589,79.958 136.94,80.309 136.589,80.309 136.238,80.66 135.888,80.309 135.537,80.309 135.888,79.958 135.537,79.607 ; 135.537,83.818 136.94,83.818 136.238,82.414 135.537,83.818
  lines w0.305: 134.264,71.994 216.344,71.994 ; 134.264,84.625 216.344,84.625 ; 142.846,68.836 142.846,87.782 ; 151.279,68.836 151.279,87.782 ; 167.448,68.836 167.448,87.782 ; 174.03,68.836 174.03,87.782 ; 183.559,68.836 183.559,87.782 ; 201.957,68.836 201.957,87.782 ; 134.264,68.836 216.344,68.836 216.344,87.782 134.264,87.782 134.264,68.836
  text "Symbol" at 136.159,85.572 h1.83
  text "Quantity" at 143.793,85.572 h1.83
  text "Finished Hole Size" at 152.226,85.572 h1.83
  text "Plated" at 168.395,85.572 h1.83
  text "Hole Type" at 174.977,85.572 h1.83
  text "Drill Layer Pair" at 184.506,85.572 h1.83
  text "Hole Tolerance" at 202.904,85.572 h1.83
  text "1" at 143.793,82.414 h1.52
  text "343.70mil (8.730mm)" at 152.226,82.414 h1.52
  text "NPTH" at 168.395,82.414 h1.52
  text "Round" at 174.977,82.414 h1.52
  text "Top Layer - Bottom Layer" at 184.506,82.414 h1.52
  text "+/-1.18mil" at 202.904,82.414 h1.52
  text "22" at 143.793,79.257 h1.52
  text "16.00mil (0.406mm)" at 152.226,79.257 h1.52
  text "PTH" at 168.395,79.257 h1.52
  text "Round" at 174.977,79.257 h1.52
  text "Top Layer - Bottom Layer" at 184.506,79.257 h1.52
  text "4" at 143.793,76.099 h1.52
  text "20.00mil (0.508mm)" at 152.226,76.099 h1.52
  text "PTH" at 168.395,76.099 h1.52
  text "Round" at 174.977,76.099 h1.52
  text "Top Layer - Bottom Layer" at 184.506,76.099 h1.52
  text "5" at 143.793,72.941 h1.52
  text "43.31mil (1.100mm)" at 152.226,72.941 h1.52
  text "PTH" at 168.395,72.941 h1.52
  text "Round" at 174.977,72.941 h1.52
  text "Top Layer - Bottom Layer" at 184.506,72.941 h1.52
  text "32 Total" at 143.793,69.783 h1.52
  text ".Layer_Name" at 14.656,-21.806 h1.52
M17 Embedded Cavity:
  text ".Layer_Name" at 14.656,-21.806 h1.52
M18 Embedded Assembly:
  text ".Layer_Name" at 14.656,-21.806 h1.52
M19 Embedded Keepout:
  text ".Layer_Name" at 14.656,-21.806 h1.52

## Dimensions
0,-10.16 to 25.4,-10.16 on M2 Board Dimensions
-0.762,17.272 to -0.762,0 on M2 Board Dimensions
-0.762,0 to 50.8,0 on M2 Board Dimensions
